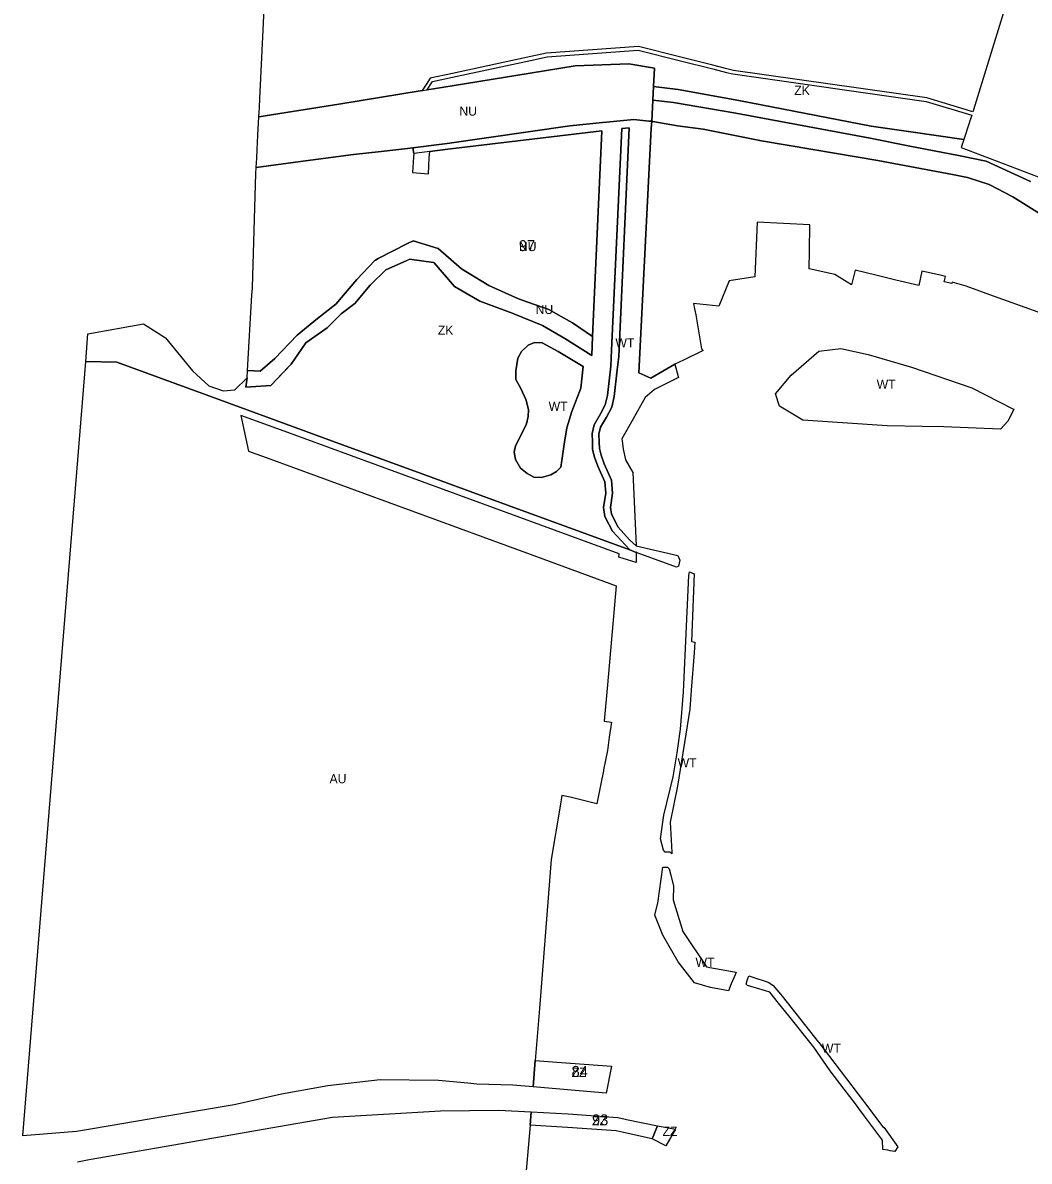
# Model space of a CAD drawing. Extents: x -545779 to -541342, y -1153413 to -1149956.
# Drawn here: x -544677 to -544124, y -1151467 to -1150842 of the extents above; entities that cross this region are included whole.
import ezdxf

# ---------------------------------------------------------------- set-up
doc = ezdxf.new("R2010")
doc.units = 0
for name, color, linetype in [('90640013', 7, 'Continuous'), ('90670013', 7, 'Continuous'), ('90670023', 7, 'Continuous'), ('90710013', 7, 'Continuous'), ('90730013', 7, 'Continuous'), ('90730023', 7, 'Continuous'), ('90750013', 7, 'Continuous'), ('90760013', 7, 'Continuous'), ('ID_navrh', 7, 'Continuous')]:
    doc.layers.add(name, color=color, linetype=linetype)

msp = doc.modelspace()

# ---------------------------------------------------------------- linework, layer by layer
at = {"layer": '90640013'}
msp.add_lwpolyline([(-544123.65, -1150929.34), (-544147.92, -1150918.16), (-544163.14, -1150915.17), (-544189.92, -1150909.92), (-544211.6, -1150905.59), (-544285.48, -1150891.85), (-544319.63, -1150885.97), (-544331.029, -1150884.669), (-544330.65, -1150877.304), (-544317.11, -1150878.83), (-544283.77, -1150884.86), (-544211.12, -1150898.96), (-544189.25, -1150902.17), (-544160.33, -1150906.42), (-544161.7, -1150910.69), (-544119.43, -1150926.78)], dxfattribs=at)
for points in [[(-544340.06, -1151129.45), (-544317.35, -1151134.76), (-544316.18, -1151137.4), (-544316.52, -1151139.06), (-544316.85, -1151140.73), (-544318.04, -1151141.16), (-544339.59, -1151133.35), (-544340.09, -1151132.86), (-544340.09, -1151133.08), (-544343.68, -1151131.77), (-544353.06, -1151121.41), (-544357.37, -1151113.3), (-544358, -1151108.49), (-544356.86, -1151100.51), (-544357.37, -1151094.3), (-544361.17, -1151085.81), (-544362.94, -1151080.74), (-544364.08, -1151076.55), (-544364.21, -1151072.63), (-544364.34, -1151067.81), (-544363.2, -1151063), (-544359.77, -1151057.04), (-544357.11, -1151051.97), (-544355.97, -1151046.9), (-544354.137, -1151030.889), (-544353.727, -1151022.126), (-544348.027, -1150900.338), (-544343.9, -1150899.85), (-544349.66, -1151025.46), (-544350.59, -1151032.901), (-544352.264, -1151047.527), (-544353.556, -1151053.276), (-544356.48, -1151058.849), (-544359.674, -1151064.398), (-544360.575, -1151068.199), (-544360.458, -1151072.517), (-544360.343, -1151075.987), (-544359.353, -1151079.627), (-544357.679, -1151084.422), (-544353.682, -1151093.353), (-544353.084, -1151100.623), (-544354.211, -1151108.512), (-544353.737, -1151112.139), (-544349.964, -1151119.237), (-544343.745, -1151126.106)], [(-544375.56, -1151055.72), (-544378.27, -1151064.61), (-544379.72, -1151073.6), (-544380.88, -1151082.59), (-544381.6, -1151086.22), (-544383.92, -1151088.69), (-544386.97, -1151090.43), (-544392.04, -1151091.88), (-544396.25, -1151091.73), (-544400.02, -1151089.85), (-544403.65, -1151086.8), (-544406.4, -1151082.16), (-544407.13, -1151078.1), (-544406.4, -1151074.62), (-544402.78, -1151067.36), (-544400.31, -1151062.43), (-544399.44, -1151058.51), (-544399.29, -1151054.74), (-544400.6, -1151049.52), (-544403.5, -1151043.14), (-544406.26, -1151038.21), (-544406.26, -1151033.42), (-544405.1, -1151026.46), (-544403.07, -1151022.68), (-544399.44, -1151019.35), (-544395.96, -1151017.75), (-544391.75, -1151018.04), (-544383.05, -1151022.68), (-544369.28, -1151030.95), (-544370.49, -1151042.82)], [(-544135.83, -1151060.82), (-544140.09, -1151065.42), (-544171.16, -1151064.15), (-544183.14, -1151063.96), (-544202.28, -1151063.65), (-544248.55, -1151060.53), (-544261.39, -1151052.79), (-544263.64, -1151046.09), (-544255.06, -1151035.76), (-544239.88, -1151022.55), (-544227.79, -1151021.07), (-544212.83, -1151024.4), (-544188.98, -1151031.43), (-544155.85, -1151042.75), (-544133.31, -1151054.25), (-544132.77, -1151054.51)], [(-544314.11, -1151209.76), (-544311.16, -1151145.77), (-544311.08, -1151144.88), (-544310.81, -1151143.81), (-544308.38, -1151144.78), (-544309.75, -1151182.11), (-544307.9, -1151182.39), (-544308.39, -1151188.2), (-544309.91, -1151208.84), (-544310.68, -1151219.21), (-544317.48, -1151261.56), (-544321.55, -1151281.26), (-544320.51, -1151297.8), (-544320.65, -1151298.6), (-544321.55, -1151297.77), (-544323, -1151297.7), (-544324.02, -1151297.65), (-544324.28, -1151297.64), (-544325.19, -1151296.57), (-544326.79, -1151290.45), (-544324.93, -1151277.46), (-544319.79, -1151256.39), (-544317.56, -1151243.24), (-544315.77, -1151230.23)], [(-544288.03, -1151370.05), (-544289.48, -1151373.85), (-544299.4, -1151372.02), (-544308.19, -1151369.5), (-544317.07, -1151357.88), (-544325.5, -1151343.33), (-544329.9, -1151332.33), (-544329.71, -1151331.38), (-544328.22, -1151325.77), (-544325.52, -1151305.99), (-544324.13, -1151306.01), (-544323.14, -1151306.03), (-544322.89, -1151306.03), (-544322.04, -1151306.84), (-544321.15, -1151310.42), (-544319.64, -1151316.49), (-544319.76, -1151323.83), (-544314.52, -1151341.22), (-544301.59, -1151360.73), (-544300.36, -1151360.94), (-544299.64, -1151361.07), (-544285.19, -1151363.57), (-544285.76, -1151365.11), (-544285.86, -1151365.099)], [(-544225.87, -1151427.83), (-544233.72, -1151417.75), (-544242.66, -1151404.79), (-544256.39, -1151387.69), (-544261.98, -1151380.65), (-544266.73, -1151374.66), (-544269.06, -1151373.86), (-544279.01, -1151370.9), (-544279.78, -1151370.16), (-544279.14, -1151368.23), (-544278.97, -1151367.71), (-544278.79, -1151367.18), (-544278.29, -1151365.66), (-544277.27, -1151366.08), (-544276.72, -1151366.25), (-544267.72, -1151369.06), (-544265.13, -1151370.74), (-544264.92, -1151370.99), (-544260.9, -1151375.62), (-544259.92, -1151376.85), (-544257.27, -1151380.2), (-544240.13, -1151401.83), (-544239.84, -1151402.21), (-544231.12, -1151413.87), (-544211.87, -1151438.99), (-544204.38, -1151449.08), (-544204.14, -1151448.78), (-544196.56, -1151459.57), (-544198.11, -1151462.14), (-544200.63, -1151461.69), (-544202.02, -1151461.44), (-544204.74, -1151460.96), (-544204.92, -1151455.91), (-544214.78, -1151442.66), (-544217.843, -1151438.564), (-544219.744, -1151436.022)]]:
    msp.add_lwpolyline(points, close=True, dxfattribs=at)
at = {"layer": '90670013'}
msp.add_lwpolyline([(-544323.85, -1151458.96), (-544331.29, -1151455.07), (-544328.51, -1151448.1), (-544323.36, -1151448.87), (-544318.6, -1151449.9)], close=True, dxfattribs=at)
at = {"layer": '90670023'}
for points in [[(-544386.22, -1151427.51), (-544396.611, -1151426.66), (-544395.653, -1151412.208), (-544383.777, -1151413.06), (-544353.737, -1151415.218), (-544353.737, -1151415.218), (-544356.61, -1151430.05)], [(-544377.931, -1151448.863), (-544398.431, -1151447.726), (-544397.794, -1151440.352), (-544377.46, -1151441.48), (-544350.17, -1151443.45), (-544346.19, -1151444.28), (-544345.38, -1151444.48), (-544328.51, -1151448.1), (-544331.29, -1151455.07), (-544347.043, -1151451.69), (-544347.832, -1151451.495), (-544351.196, -1151450.793)]]:
    msp.add_lwpolyline(points, close=True, dxfattribs=at)
at = {"layer": '90710013'}
for points in [[(-544398.42, -1150869.95), (-544441.24, -1150876.85), (-544454.93, -1150879.06), (-544453.08, -1150876.18), (-544451.94, -1150874.42), (-544441.01, -1150872.08), (-544398.09, -1150862.89), (-544389.1, -1150860.97), (-544339.08, -1150857.24), (-544315.79, -1150863.12), (-544298.12, -1150867.58), (-544290.46, -1150869.51), (-544287.16, -1150870.34), (-544180.94, -1150885.41), (-544155.87, -1150893.02), (-544156.18, -1150894.03), (-544156.62, -1150895.12), (-544156.98, -1150896.02), (-544157.4, -1150897.33), (-544160.33, -1150906.42), (-544189.25, -1150902.17), (-544211.12, -1150898.96), (-544283.77, -1150884.86), (-544317.11, -1150878.83), (-544330.65, -1150877.304), (-544330.131, -1150867.233), (-544344.25, -1150864.77), (-544373.58, -1150865.95)], [(-544331.63, -1150896.329), (-544331.83, -1150900.22), (-544338.74, -1151034.41), (-544332.14, -1151037.33), (-544318.86, -1151029.7), (-544317.11, -1151036.5), (-544316.92, -1151037.05), (-544330.07, -1151043.55), (-544335.18, -1151048.11), (-544342.02, -1151060.09), (-544348.07, -1151070.69), (-544347.85, -1151071.82), (-544347.27, -1151076.35), (-544346, -1151082.21), (-544341.92, -1151089.17), (-544341.74, -1151093.07), (-544340.06, -1151129.45), (-544343.745, -1151126.106), (-544349.964, -1151119.237), (-544353.737, -1151112.139), (-544354.211, -1151108.512), (-544353.084, -1151100.623), (-544353.682, -1151093.353), (-544357.679, -1151084.422), (-544359.353, -1151079.627), (-544360.343, -1151075.987), (-544360.458, -1151072.517), (-544360.575, -1151068.199), (-544359.674, -1151064.398), (-544356.48, -1151058.849), (-544353.556, -1151053.276), (-544352.264, -1151047.527), (-544350.59, -1151032.901), (-544349.66, -1151025.46), (-544343.9, -1150899.85), (-544348.027, -1150900.338), (-544353.727, -1151022.126), (-544354.137, -1151030.889), (-544355.97, -1151046.9), (-544357.11, -1151051.97), (-544359.77, -1151057.04), (-544363.2, -1151063), (-544364.34, -1151067.81), (-544364.21, -1151072.63), (-544364.08, -1151076.55), (-544362.94, -1151080.74), (-544361.17, -1151085.81), (-544357.37, -1151094.3), (-544356.86, -1151100.51), (-544358, -1151108.49), (-544357.37, -1151113.3), (-544353.06, -1151121.41), (-544343.68, -1151131.77), (-544422.333, -1151102.983), (-544456.22, -1151090.58), (-544501.351, -1151074.059), (-544568.77, -1151049.38), (-544625.23, -1151028.57), (-544642.403, -1151028.226), (-544641.174, -1151013.082), (-544610.7, -1151007.65), (-544598.59, -1151015.3), (-544583.69, -1151033.44), (-544574.77, -1151041.7), (-544566.94, -1151044.29), (-544560.43, -1151043.82), (-544553.7, -1151037.15), (-544554.49, -1151042.43), (-544540.76, -1151041.46), (-544529.59, -1151029.68), (-544521.6, -1151018.02), (-544509.72, -1151009.75), (-544502.11, -1151002.05), (-544494.55, -1150996.43), (-544486.23, -1150986.27), (-544477.68, -1150977.83), (-544466.369, -1150972.922), (-544464.59, -1150972.15), (-544451.49, -1150973.87), (-544451.31, -1150973.89), (-544451.13, -1150974.1), (-544439.85, -1150987.13), (-544425.91, -1150995.14), (-544407.612, -1151001.954), (-544407.3, -1151002.07), (-544391.6, -1151008.56), (-544379.36, -1151015.61), (-544364.41, -1151024.94), (-544364.12, -1151014.56), (-544358.93, -1150901.63), (-544443.54, -1150911.65), (-544453.51, -1150912.96), (-544462.3, -1150914.11), (-544462.703, -1150910.899), (-544443.91, -1150908.54), (-544376.63, -1150898.77), (-544358.719, -1150897.037), (-544356.47, -1150896.82), (-544341.39, -1150895.37), (-544333.16, -1150896.18)], [(-544391.75, -1151018.04), (-544395.96, -1151017.75), (-544399.44, -1151019.35), (-544403.07, -1151022.68), (-544405.1, -1151026.46), (-544406.26, -1151033.42), (-544406.26, -1151038.21), (-544403.5, -1151043.14), (-544400.6, -1151049.52), (-544399.29, -1151054.74), (-544399.44, -1151058.51), (-544400.31, -1151062.43), (-544402.78, -1151067.36), (-544406.4, -1151074.62), (-544407.13, -1151078.1), (-544406.4, -1151082.16), (-544403.65, -1151086.8), (-544400.02, -1151089.85), (-544396.25, -1151091.73), (-544392.04, -1151091.88), (-544386.97, -1151090.43), (-544383.92, -1151088.69), (-544381.6, -1151086.22), (-544380.88, -1151082.59), (-544379.72, -1151073.6), (-544378.27, -1151064.61), (-544375.56, -1151055.72), (-544370.49, -1151042.82), (-544369.28, -1151030.95), (-544383.05, -1151022.68)]]:
    msp.add_lwpolyline(points, close=True, dxfattribs=at)
msp.add_lwpolyline([(-544092.35, -1150963.53), (-544133.39, -1150937.74), (-544146.34, -1150931.13), (-544158.14, -1150927.27), (-544166.52, -1150925.65), (-544183.95, -1150922.29), (-544207.45, -1150917.93), (-544243.2, -1150911.81), (-544271.36, -1150907), (-544303.43, -1150900.67), (-544317.51, -1150898.82), (-544331.01, -1150896.39), (-544331.63, -1150896.329), (-544331.029, -1150884.669), (-544319.63, -1150885.97), (-544285.48, -1150891.85), (-544211.6, -1150905.59), (-544189.92, -1150909.92), (-544163.14, -1150915.17), (-544147.92, -1150918.16), (-544123.65, -1150929.34)], dxfattribs=at)
at = {"layer": '90730013'}
for points in [[(-544524.378, -1150918.456), (-544548.85, -1150921.72), (-544548.51, -1150916.54), (-544548.25, -1150912.06), (-544547.79, -1150904.05), (-544547.26, -1150893.94), (-544503.41, -1150886.87), (-544457.6, -1150879.49), (-544457.14, -1150879.42), (-544455.39, -1150879.13), (-544454.93, -1150879.06), (-544441.24, -1150876.85), (-544398.42, -1150869.95), (-544373.58, -1150865.95), (-544344.25, -1150864.77), (-544330.131, -1150867.233), (-544330.65, -1150877.304), (-544331.029, -1150884.669), (-544331.63, -1150896.329), (-544333.16, -1150896.18), (-544341.39, -1150895.37), (-544356.47, -1150896.82), (-544358.719, -1150897.037), (-544376.63, -1150898.77), (-544443.91, -1150908.54), (-544465.66, -1150911.27), (-544480.24, -1150912.9), (-544495.32, -1150914.58)], [(-544531.369, -1151031.556), (-544540.76, -1151041.46), (-544554.49, -1151042.43), (-544553.7, -1151037.15), (-544553.55, -1151033.12), (-544546.68, -1151033.61), (-544546.68, -1151033.61), (-544538.49, -1151026.65), (-544526.34, -1151013.77), (-544515.04, -1151004.73), (-544505.06, -1150996.81), (-544493.45, -1150983.24), (-544483.56, -1150972.71), (-544483.29, -1150972.57), (-544481.75, -1150971.78), (-544465.64, -1150963.49), (-544462.56, -1150961.91), (-544448.77, -1150966.14), (-544436.03, -1150977.33), (-544420.96, -1150986.53), (-544404.76, -1150993.88), (-544399.72, -1150995.64), (-544388.04, -1150999.72), (-544381.37, -1151003.47), (-544375.05, -1151007.02), (-544364.12, -1151014.56), (-544364.41, -1151024.94), (-544379.36, -1151015.61), (-544391.6, -1151008.56), (-544407.3, -1151002.07), (-544407.612, -1151001.954), (-544425.91, -1150995.14), (-544439.85, -1150987.13), (-544451.13, -1150974.1), (-544451.31, -1150973.89), (-544451.49, -1150973.87), (-544464.59, -1150972.15), (-544464.619, -1150972.163), (-544466.369, -1150972.922), (-544477.68, -1150977.83), (-544486.23, -1150986.27), (-544494.55, -1150996.43), (-544502.11, -1151002.05), (-544509.72, -1151009.75), (-544521.6, -1151018.02), (-544529.59, -1151029.68), (-544531.369, -1151031.556)]]:
    msp.add_lwpolyline(points, close=True, dxfattribs=at)
at = {"layer": '90730023'}
msp.add_lwpolyline([(-544443.54, -1150911.65), (-544358.93, -1150901.63), (-544364.12, -1151014.56), (-544375.05, -1151007.02), (-544381.37, -1151003.47), (-544388.04, -1150999.72), (-544399.72, -1150995.64), (-544404.76, -1150993.88), (-544420.96, -1150986.53), (-544436.03, -1150977.33), (-544448.77, -1150966.14), (-544462.56, -1150961.91), (-544465.64, -1150963.49), (-544481.75, -1150971.78), (-544483.29, -1150972.57), (-544483.56, -1150972.71), (-544493.45, -1150983.24), (-544505.06, -1150996.81), (-544515.04, -1151004.73), (-544526.34, -1151013.77), (-544538.49, -1151026.65), (-544546.68, -1151033.61), (-544553.55, -1151033.12), (-544551.1, -1150991.78), (-544550.88, -1150988.05), (-544550.86, -1150987.66), (-544548.95, -1150924.97), (-544548.85, -1150921.72), (-544524.378, -1150918.456), (-544495.32, -1150914.58), (-544480.24, -1150912.9), (-544465.66, -1150911.27), (-544462.703, -1150910.899), (-544462.3, -1150914.11), (-544462.43, -1150916.09), (-544462.92, -1150924.5), (-544454.2, -1150925.15), (-544453.72, -1150916.42), (-544453.51, -1150912.96)], close=True, dxfattribs=at)
at = {"layer": '90750013'}
for points in [[(-544138.43, -1150836.61), (-544154.97, -1150890.12), (-544155.31, -1150891.22), (-544180.51, -1150883.46), (-544286.78, -1150868.37), (-544290.38, -1150867.46), (-544298.04, -1150865.53), (-544315.7, -1150861.08), (-544338.91, -1150855.23), (-544389.37, -1150858.98), (-544397.99, -1150860.82), (-544440.91, -1150870.01), (-544453.18, -1150872.64), (-544455.47, -1150876.18), (-544457.6, -1150879.49), (-544503.41, -1150886.87), (-544547.26, -1150893.94), (-544547.13, -1150891.57), (-544546.9, -1150888.64), (-544546.73, -1150884.03), (-544540.66, -1150758.74)], [(-544646.97, -1151467.7), (-544640.54, -1151466.58), (-544593.95, -1151458.46), (-544540.71, -1151449.17), (-544506.92, -1151443.28), (-544447.61, -1151439.82), (-544415.66, -1151439.36), (-544397.794, -1151440.352), (-544398.431, -1151447.726), (-544404.191, -1151514.379)]]:
    msp.add_lwpolyline(points, dxfattribs=at)
msp.add_lwpolyline([(-544676.935, -1151453.593), (-544642.403, -1151028.226), (-544625.23, -1151028.57), (-544568.77, -1151049.38), (-544501.351, -1151074.059), (-544456.22, -1151090.58), (-544422.333, -1151102.983), (-544343.68, -1151131.77), (-544340.09, -1151133.08), (-544340.12, -1151136.85), (-544340.12, -1151137.33), (-544340.13, -1151138.59), (-544349.7, -1151135.7), (-544349.539, -1151133.883), (-544392.55, -1151118.14), (-544535.48, -1151065.83), (-544535.48, -1151065.83), (-544557.159, -1151057.889), (-544552.912, -1151077.549), (-544541.325, -1151081.794), (-544398.393, -1151134.104), (-544351.093, -1151151.417), (-544355.92, -1151205.89), (-544357.7, -1151225.87), (-544353.73, -1151226.36), (-544354.93, -1151234.65), (-544355.95, -1151241.9), (-544358.05, -1151252.48), (-544358.15, -1151252.98), (-544359.55, -1151260.12), (-544361.72, -1151271.16), (-544376.33, -1151267.55), (-544380.945, -1151266.525), (-544381.96, -1151272.53), (-544386.893, -1151301.708), (-544393.254, -1151383.494), (-544395.653, -1151412.208), (-544396.611, -1151426.66), (-544407.86, -1151425.74), (-544427.72, -1151425.05), (-544432.64, -1151424.59), (-544448.69, -1151423.1), (-544480.64, -1151422.82), (-544509.45, -1151426.08), (-544534.87, -1151430.66), (-544560.82, -1151436.56), (-544598.93, -1151442.97), (-544638.67, -1151449.66), (-544647.37, -1151451.12)], close=True, dxfattribs=at)
at = {"layer": '90760013'}
msp.add_lwpolyline([(-544119.396, -1151001.178), (-544145.906, -1150991.608), (-544159.03, -1150986.87), (-544166.56, -1150984.76), (-544166.85, -1150985.46), (-544171.09, -1150984.55), (-544170.39, -1150981.51), (-544173.93, -1150980.64), (-544183.27, -1150978.58), (-544184.946, -1150986.464), (-544197.54, -1150983.58), (-544208.58, -1150980.92), (-544219.85, -1150978.19), (-544221.95, -1150986.09), (-544231.07, -1150980.53), (-544245.1, -1150977.32), (-544245.06, -1150967.45), (-544244.73, -1150953.19), (-544273.79, -1150951.78), (-544275.03, -1150981.73), (-544289.15, -1150984.01), (-544294.75, -1150997.87), (-544308.64, -1150996.44), (-544308.03, -1150999.33), (-544307.45, -1151002.7), (-544304.25, -1151021.22), (-544303.38, -1151022.3), (-544314.12, -1151027.52), (-544318.86, -1151029.7), (-544332.14, -1151037.33), (-544338.74, -1151034.41), (-544331.83, -1150900.22), (-544331.63, -1150896.329), (-544331.01, -1150896.39), (-544317.51, -1150898.82), (-544303.43, -1150900.67), (-544271.36, -1150907), (-544243.2, -1150911.81), (-544207.45, -1150917.93), (-544183.95, -1150922.29), (-544166.52, -1150925.65), (-544158.14, -1150927.27), (-544146.34, -1150931.13), (-544133.39, -1150937.74), (-544092.35, -1150963.53)], dxfattribs=at)

# ---------------------------------------------------------------- texts
at = {"layer": '90640013'}
for rotation, p in [(0, (-544351.542, -1151020.505)), (0, (-544208.078, -1151043.245)), (0, (-544388.205, -1151055.357)), (360, (-544317.345, -1151251.198)), (360, (-544307.545, -1151360.715)), (0, (-544238.17, -1151407.871))]:
    msp.add_text('WT', height=5, rotation=rotation, dxfattribs=at).set_placement(p)
at = {"layer": '90670013'}
msp.add_text('ZZ', height=5, rotation=0, dxfattribs=at).set_placement((-544325.69, -1151453.53))
at = {"layer": '90670023'}
for p in [(-544375.563, -1151421.129), (-544364.376, -1151447.711)]:
    msp.add_text('ZZ', height=5, rotation=0, dxfattribs=at).set_placement(p)
at = {"layer": '90710013'}
for rotation, p in [(0, (-544253.348, -1150881.83)), (360, (-544449.055, -1151013.57))]:
    msp.add_text('ZK', height=5, rotation=rotation, dxfattribs=at).set_placement(p)
at = {"layer": '90730013'}
msp.add_text('NU', height=5, dxfattribs=at).set_placement((-544437.21, -1150893.245))
msp.add_text('NU', height=5, rotation=0, dxfattribs=at).set_placement((-544395.37, -1151002.17))
at = {"layer": '90730023'}
msp.add_text('NU', height=5, rotation=360, dxfattribs=at).set_placement((-544404.524, -1150967.62))
at = {"layer": '90750013'}
msp.add_text('AU', height=5, rotation=360, dxfattribs=at).set_placement((-544508.512, -1151259.888))
at = {"layer": 'ID_navrh'}
for s, rotation, p in [('97', 360, (-544404.524, -1150967.62)), ('84', 0, (-544375.563, -1151421.129)), ('93', 0, (-544364.376, -1151447.711))]:
    msp.add_text(s, height=6, rotation=rotation, dxfattribs=at).set_placement(p)

doc.saveas('drawing.dxf')
